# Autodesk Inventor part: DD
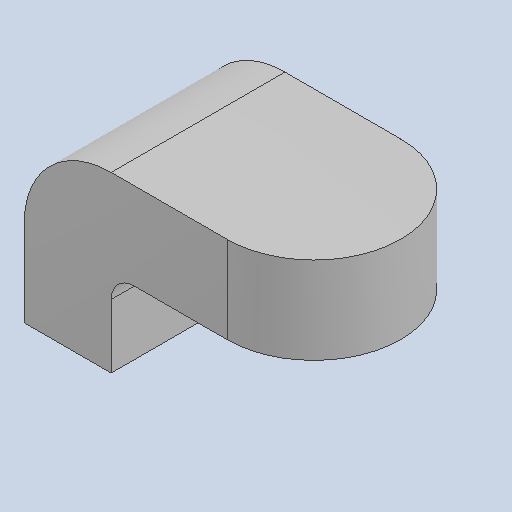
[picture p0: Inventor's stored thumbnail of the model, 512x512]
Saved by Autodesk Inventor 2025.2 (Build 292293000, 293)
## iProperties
Created: 2025-04
Part Number: DD
Material: Generic
Description: NOT SPECIFIED
Document SubType Name: Modeling
Designer: BennF
Density: 1 g/cm^3
Appearance: Default
Author: BennF
Revision Number: 2LAST_VERSION
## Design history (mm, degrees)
feature "Base1"
body "Solid1"
